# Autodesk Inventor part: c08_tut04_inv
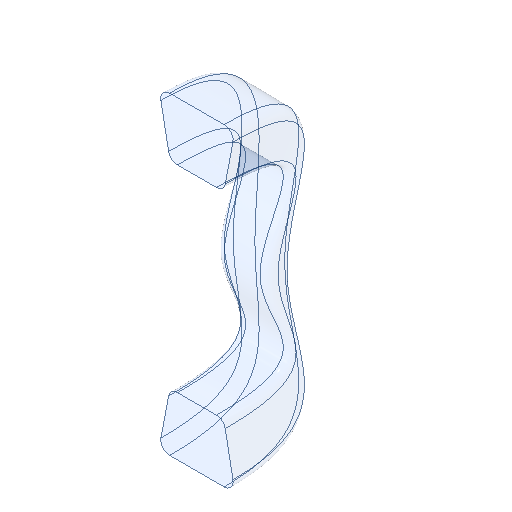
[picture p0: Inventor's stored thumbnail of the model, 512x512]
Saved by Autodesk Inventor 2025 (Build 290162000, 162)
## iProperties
Created: 2015-03
Part Number: c08_tut04_inv
Material: Generic
Document SubType Name: Modeling
Designer: Sandeep
Density: 1 g/cm^3
Appearance: Blue - Glazing
Mass: 996.637 g
Surface Area: 881.078 cm^2
Volume: 996.637 cm^3
Author: Sandeep
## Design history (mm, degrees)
sketch "Sketch1"
  geometry: L1 (-20, 50.541)-(20, 50.541); L2 (30, 60.541)-(30, 70.541); L3 (-30, 60.541)-(-30, 70.541); L4 (0, -9.695)-(0, 120.745); L5 (0, 82)-(-105.666, 82); A1 r 45 centre (0, 37) between (30, 70.541) and (-30, 70.541); A2 r 10 centre (-20, 60.541) between (-30, 60.541) and (-20, 50.541); A3 r 10 centre (20, 60.541) between (20, 50.541) and (30, 60.541); 2 further points
  constraints: 10 end point, 7 point on circle, 5 point on line, 4 tangent, 3 centre point, 2 horizontal, 2 vertical, 1 perpendicular, 1 other
  dimensions: "d0" = 60 distance between parallel lines of L2 L3; "d2" = 20 distance of point (30, 50.541) L2.end; "d3" = 45 radius of A1; "d4" = 10 radius of A2; "d5" = 10 radius of A3; "d22" = 82 distance from line of point (0, 0) L5
sketch "Sketch2"
  geometry: L1 (30.394, 175)-(-30.394, 175); L2 (-40.214, 163.112)-(-31.56, 118.112); L3 (-21.74, 110)-(21.74, 110); L4 (31.56, 118.112)-(40.214, 163.112); L5 (0, 0)-(0, 325.346); A1 r 10 centre (30.394, 165) between (40.214, 163.112) and (30.394, 175); A2 r 10 centre (-30.394, 165) between (-30.394, 175) and (-40.214, 163.112); A3 r 10 centre (-21.74, 120) between (-31.56, 118.112) and (-21.74, 110); A4 r 10 centre (21.74, 120) between (21.74, 110) and (31.56, 118.112); 4 further points
  constraints: 10 end point, 8 point on circle, 8 point on line, 8 tangent, 4 centre point, 3 equal radius, 1 horizontal, 1 parallel, 1 vertical, 1 other
  dimensions: "d6" = 60 distance of point (-30, 110) point (30, 110); "d7" = 65 distance between parallel lines of L1 L3; "d8" = 85 distance of point (42.5, 175) point (-42.5, 175); "d9" = 175 distance from line of L5.start L1; "d10" = 10 radius of A1
loft "Loft2" sketch "Sketch1", "Sketch2" dims "d23" = 50, "d24" = 90 deg, "d25" = 0, "d26" = 90 deg, "d27" = 50, "d28" = 90 deg
body "Solid2"
sketch "Sketch3"
  geometry: L1 (21.74, -110)-(-21.74, -110); L2 (-31.56, -118.112)-(-40.214, -163.112); L3 (-30.394, -175)-(30.394, -175); L4 (40.214, -163.112)-(31.56, -118.112); L5 (0, 0)-(0, -235.653); A1 r 10 centre (-30.394, -165) between (-40.214, -163.112) and (-30.394, -175); A2 r 10 centre (30.394, -165) between (30.394, -175) and (40.214, -163.112); A3 r 10 centre (21.74, -120) between (31.56, -118.112) and (21.74, -110); A4 r 10 centre (-21.74, -120) between (-21.74, -110) and (-31.56, -118.112); 4 further points
  constraints: 10 end point, 8 point on circle, 8 point on line, 8 tangent, 4 centre point, 3 equal radius, 1 horizontal, 1 parallel, 1 vertical, 1 other
  dimensions: "d11" = 60 distance of point (30, -110) point (-30, -110); "d12" = 85 distance of point (-42.5, -175) point (42.5, -175); "d13" = 65 distance between parallel lines of L1 L3; "d14" = 175 distance from line of L5.start L3; "d15" = 10 radius of A1
